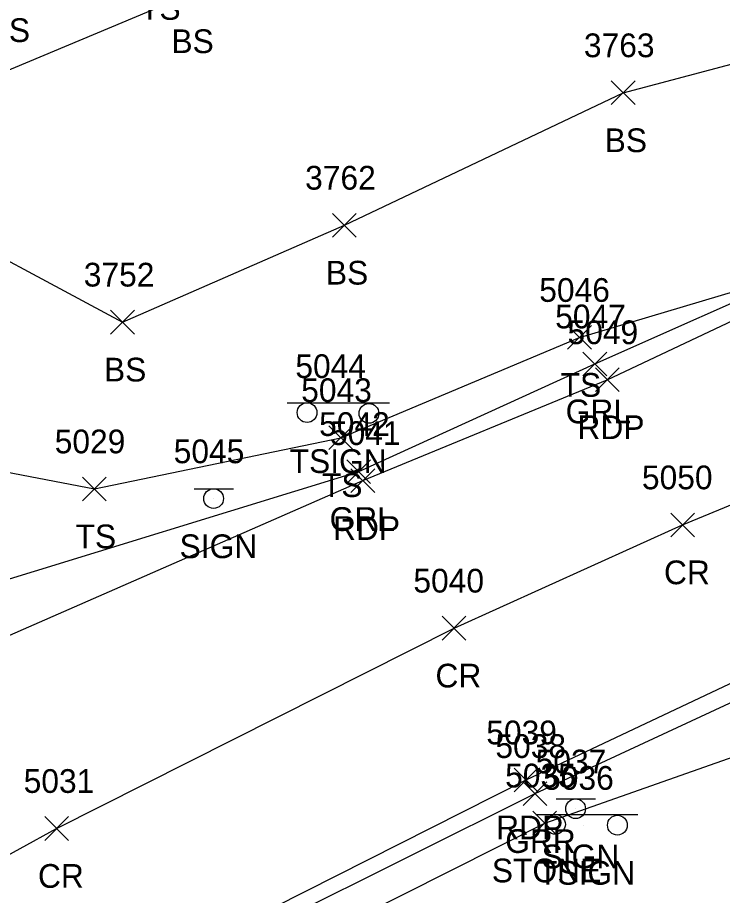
# Model space of a CAD drawing. Extents: x 1505656 to 1508446, y 700805 to 703031.
# Drawn here: x 1506352.2 to 1506411.5, y 701736.4 to 701810.4 of the extents above; entities that cross this region are included whole.
import ezdxf

# ---------------------------------------------------------------- set-up
doc = ezdxf.new("R2010")
doc.units = 0
for name, color, linetype in [('L_A', 7, 'Continuous'), ('L_I', 7, 'Continuous'), ('L_TIC', 7, 'Continuous'), ('LASF', 7, 'Continuous'), ('LELB', 7, 'Continuous'), ('P_A', 7, 'Continuous'), ('P_I', 7, 'Continuous'), ('P_TIC', 7, 'Continuous'), ('PET', 7, 'Continuous'), ('PRC', 7, 'Continuous'), ('R_A', 7, 'Continuous'), ('R_I', 7, 'Continuous'), ('R_TIC', 7, 'Continuous'), ('RGR', 7, 'Continuous'), ('S_A', 7, 'Continuous'), ('S_I', 7, 'Continuous'), ('SSGN', 7, 'Continuous')]:
    doc.layers.add(name, color=color, linetype=linetype)

msp = doc.modelspace()

# ---------------------------------------------------------------- linework, layer by layer
at = {"layer": 'L_TIC'}
for points in [[(1506402.157, 701803.045), (1506404.157, 701805.045)], [(1506404.157, 701803.045), (1506402.157, 701805.045)], [(1506378.684, 701791.884), (1506380.684, 701793.884)], [(1506380.684, 701791.884), (1506378.684, 701793.884)], [(1506359.998, 701783.718), (1506361.998, 701785.718)], [(1506361.998, 701783.718), (1506359.998, 701785.718)], [(1506398.483, 701782.427), (1506400.483, 701784.427)], [(1506400.483, 701782.427), (1506398.483, 701784.427)], [(1506378.385, 701773.982), (1506380.385, 701775.982)], [(1506380.385, 701773.982), (1506378.385, 701775.982)], [(1506357.635, 701769.662), (1506359.635, 701771.662)], [(1506359.635, 701769.662), (1506357.635, 701771.662)], [(1506395.556, 701741.509), (1506397.556, 701743.509)], [(1506397.556, 701741.509), (1506395.556, 701743.509)]]:
    msp.add_lwpolyline(points, dxfattribs=at)
at = {"layer": 'LASF'}
msp.add_lwpolyline([(1506429.678, 701752.829), (1506443.794, 701749.581), (1506462.702, 701738.246), (1506448, 701734.792), (1506439.124, 701730.659), (1506414.696, 701723.702), (1506383.006, 701711.364), (1506356.511, 701697.302), (1506322.231, 701673.417), (1506294.027, 701680.479), (1506288.733, 701684.493), (1506312.049, 701697.87), (1506364.791, 701726.476), (1506396.556, 701742.509), (1506417.454, 701749.861)], dxfattribs=at)
at = {"layer": 'LELB'}
for points in [[(1506334.147, 701809.13), (1506349.541, 701805.202), (1506366.676, 701812.391), (1506381.989, 701819.877), (1506387.598, 701843.403)], [(1506313.579, 701798.313), (1506329.628, 701800.267), (1506343.194, 701794.26), (1506360.998, 701784.718), (1506379.684, 701792.884), (1506403.157, 701804.045), (1506415.959, 701807.446), (1506430.337, 701803.305), (1506438.861, 701796.519), (1506455.957, 701771.996), (1506464.526, 701767.062), (1506468.287, 701757.431), (1506462.702, 701738.246), (1506453.058, 701729.727), (1506439.124, 701730.659)], [(1506300.958, 701795.085), (1506316.411, 701786.525), (1506332.206, 701780.076), (1506347.055, 701772.901), (1506358.635, 701770.662), (1506379.385, 701774.982), (1506399.483, 701783.427), (1506418.587, 701789.112)]]:
    msp.add_lwpolyline(points, dxfattribs=at)
at = {"layer": 'P_TIC'}
for points in [[(1506400.819, 701778.863), (1506402.819, 701780.863)], [(1506402.819, 701778.863), (1506400.819, 701780.863)], [(1506380.237, 701770.364), (1506382.237, 701772.364)], [(1506382.237, 701770.364), (1506380.237, 701772.364)], [(1506407.16, 701766.632), (1506409.16, 701768.632)], [(1506409.16, 701766.632), (1506407.16, 701768.632)], [(1506387.918, 701757.929), (1506389.918, 701759.929)], [(1506389.918, 701757.929), (1506387.918, 701759.929)], [(1506393.976, 701745.14), (1506395.976, 701747.14)], [(1506395.976, 701745.14), (1506393.976, 701747.14)], [(1506354.448, 701741.047), (1506356.448, 701743.047)], [(1506356.448, 701741.047), (1506354.448, 701743.047)]]:
    msp.add_lwpolyline(points, dxfattribs=at)
at = {"layer": 'PET'}
for points in [[(1505981.006, 701553.678), (1506020.042, 701573.54), (1506047.431, 701586.837), (1506064.358, 701596.593), (1506091.544, 701613.44), (1506142.348, 701641.395), (1506170.767, 701656.919), (1506194.974, 701672.056), (1506198.416, 701673.569), (1506217.275, 701683.911), (1506272.213, 701715.609), (1506302.202, 701733.141), (1506348.086, 701756.841), (1506381.237, 701771.364), (1506401.819, 701779.863), (1506418.982, 701787.961), (1506419.65, 701788.001)], [(1505992.817, 701526.624), (1506019.676, 701536.958), (1506041.116, 701547.384), (1506078.94, 701568.615), (1506107.142, 701585.715), (1506155.421, 701613.403), (1506197.612, 701637.132), (1506235.983, 701659.239), (1506270.791, 701679.063), (1506309.699, 701700.773), (1506363.103, 701730.014), (1506394.976, 701746.14), (1506415.623, 701755.889), (1506435.042, 701763.8), (1506427.314, 701775.566), (1506419.65, 701788.001)]]:
    msp.add_lwpolyline(points, dxfattribs=at)
at = {"layer": 'PRC'}
msp.add_lwpolyline([(1505987.003, 701541.071), (1506027.822, 701560.696), (1506054.365, 701574.523), (1506099.991, 701598.76), (1506149.976, 701626.577), (1506191.412, 701650.145), (1506228.115, 701670.573), (1506265.762, 701691.976), (1506306.452, 701715.073), (1506355.448, 701742.047), (1506388.918, 701758.929), (1506408.16, 701767.632), (1506427.314, 701775.566)], dxfattribs=at)
at = {"layer": 'R_TIC'}
for points in [[(1506399.77, 701780.194), (1506401.77, 701782.194)], [(1506401.77, 701780.194), (1506399.77, 701782.194)], [(1506379.893, 701771.124), (1506381.893, 701773.124)], [(1506381.893, 701771.124), (1506379.893, 701773.124)], [(1506394.736, 701743.988), (1506396.736, 701745.988)], [(1506396.736, 701743.988), (1506394.736, 701745.988)]]:
    msp.add_lwpolyline(points, dxfattribs=at)
at = {"layer": 'RGR'}
for points in [[(1506348.173, 701762.078), (1506380.893, 701772.124), (1506400.77, 701781.194), (1506418.587, 701789.112)], [(1506085.731, 701568.293), (1506107.536, 701584.715), (1506155.805, 701612.355), (1506198.197, 701636.56), (1506236.662, 701658.363), (1506270.986, 701677.916), (1506310.509, 701699.403), (1506363.656, 701728.976), (1506395.736, 701744.988), (1506415.681, 701754.264), (1506427.009, 701758.86)]]:
    msp.add_lwpolyline(points, dxfattribs=at)
at = {"layer": 'SSGN'}
for p, q in [((1506374.876, 701777.929), (1506383.473, 701777.929)), ((1506378.898, 701777.025), (1506378.898, 701777.025)), ((1506367.02, 701770.684), (1506370.354, 701770.684)), ((1506368.667, 701769.851), (1506368.667, 701769.851)), ((1506397.503, 701744.544), (1506400.836, 701744.544)), ((1506395.794, 701743.231), (1506404.391, 701743.231)), ((1506399.15, 701743.711), (1506399.15, 701743.711)), ((1506399.816, 701742.327), (1506399.816, 701742.327))]:
    msp.add_line(p, q, dxfattribs=at)
for centre in [(1506376.537, 701777.095), (1506381.752, 701777.025), (1506368.667, 701769.851), (1506399.15, 701743.711), (1506397.455, 701742.397), (1506402.67, 701742.327)]:
    msp.add_circle(centre, 0.833, dxfattribs=at)

# ---------------------------------------------------------------- texts
at = {"layer": 'L_A'}
for s, p in [('TS', (1506362.477, 701810.198)), ('TS', (1506349.798, 701808.323)), ('BS', (1506365.117, 701807.391)), ('BS', (1506401.598, 701799.045)), ('BS', (1506378.125, 701787.884)), ('BS', (1506359.439, 701779.718)), ('TS', (1506397.892, 701778.427)), ('TS', (1506377.794, 701769.982)), ('TS', (1506357.045, 701765.662)), ('STONE', (1506392.099, 701737.509))]:
    msp.add_text(s, height=2, dxfattribs=at).set_placement(p)
at = {"layer": 'L_I'}
for s, p in [('3763', (1506399.85, 701807.045)), ('3762', (1506376.377, 701795.884)), ('3752', (1506357.738, 701787.718)), ('5046', (1506396.089, 701786.427)), ('5043', (1506376.046, 701777.982)), ('5029', (1506355.289, 701773.662)), ('5035', (1506393.218, 701745.509))]:
    msp.add_text(s, height=2, dxfattribs=at).set_placement(p)
at = {"layer": 'P_A'}
for s, p in [('RDP', (1506399.307, 701774.863)), ('RDP', (1506378.725, 701766.364)), ('CR', (1506406.593, 701762.632)), ('CR', (1506387.351, 701753.929)), ('RDP', (1506392.465, 701741.14)), ('CR', (1506353.881, 701737.047))]:
    msp.add_text(s, height=2, dxfattribs=at).set_placement(p)
at = {"layer": 'P_I'}
for s, p in [('5049', (1506398.472, 701782.863)), ('5041', (1506378.465, 701774.364)), ('5050', (1506404.735, 701770.632)), ('5040', (1506385.493, 701761.929)), ('5039', (1506391.63, 701749.14)), ('5031', (1506352.676, 701745.047))]:
    msp.add_text(s, height=2, dxfattribs=at).set_placement(p)
at = {"layer": 'R_A'}
for s, p in [('GRL', (1506398.313, 701776.194)), ('GRL', (1506378.436, 701767.124)), ('GRR', (1506393.224, 701739.988))]:
    msp.add_text(s, height=2, dxfattribs=at).set_placement(p)
at = {"layer": 'R_I'}
for s, p in [('5047', (1506397.431, 701784.194)), ('5042', (1506377.554, 701775.124)), ('5038', (1506392.397, 701747.988))]:
    msp.add_text(s, height=2, dxfattribs=at).set_placement(p)
at = {"layer": 'S_A'}
for s, p in [('TSIGN', (1506375.074, 701772.008)), ('SIGN', (1506365.805, 701764.83)), ('SIGN', (1506396.288, 701738.69)), ('TSIGN', (1506395.992, 701737.309))]:
    msp.add_text(s, height=2, dxfattribs=at).set_placement(p)
at = {"layer": 'S_I'}
for s, p in [('5044', (1506375.554, 701780.008)), ('5045', (1506365.309, 701772.83)), ('5037', (1506395.792, 701746.69)), ('5036', (1506396.417, 701745.309))]:
    msp.add_text(s, height=2, dxfattribs=at).set_placement(p)

doc.saveas('drawing.dxf')
